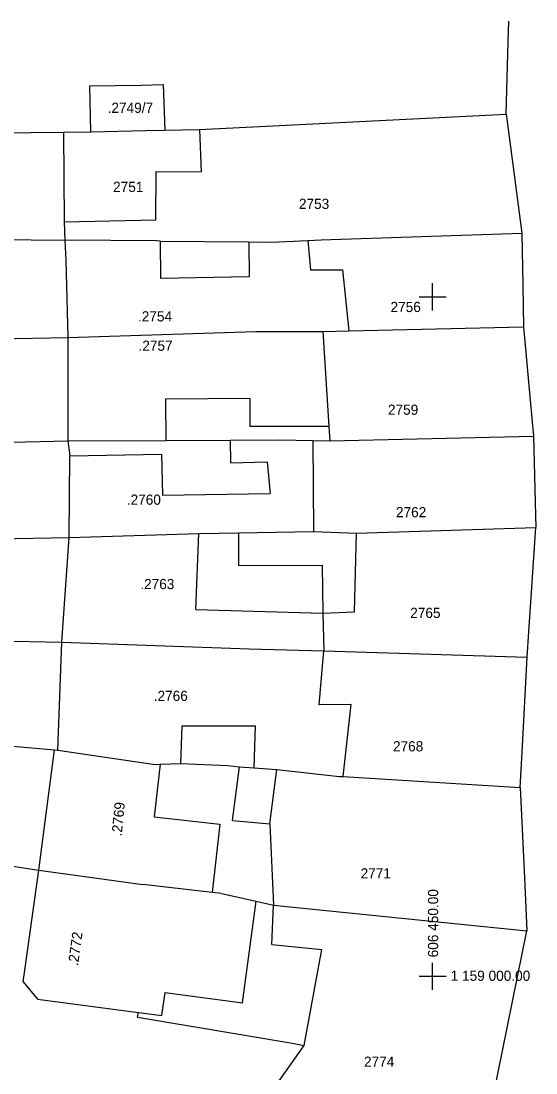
# Model space of a CAD drawing. Extents: x -606541 to -606327, y -1159083 to -1158785.
# Drawn here: x -606480.3 to -606442.4, y -1159007.1 to -1158929.7 of the extents above; entities that cross this region are included whole.
import ezdxf

# ---------------------------------------------------------------- set-up
doc = ezdxf.new("R2010")
doc.units = 0
for name, color, linetype in [('KN_HRAN_PARCEL', 7, 'Continuous'), ('KN_PARC_Č', 7, 'Continuous'), ('KN_VKP_HRAN_', 7, 'Continuous'), ('TISK_rám', 7, 'Continuous')]:
    doc.layers.add(name, color=color, linetype=linetype)

msp = doc.modelspace()

# ---------------------------------------------------------------- linework, layer by layer
at = {"layer": 'KN_HRAN_PARCEL'}
for p, q in [((-606444.44, -1158931.2), (-606444.39, -1158929.7)), ((-606444.6, -1158936.55), (-606444.44, -1158931.2)), ((-606467.14, -1158937.69), (-606444.6, -1158936.55)), ((-606444.6, -1158936.55), (-606444.11, -1158940.26)), ((-606500.53, -1158938.03), (-606477.16, -1158937.89)), ((-606477.16, -1158937.89), (-606475.15, -1158937.85)), ((-606477.16, -1158937.89), (-606477.11, -1158944.48)), ((-606475.15, -1158937.85), (-606471.11, -1158937.77)), ((-606471.11, -1158937.77), (-606469.71, -1158937.74)), ((-606469.71, -1158937.74), (-606467.14, -1158937.69)), ((-606467.14, -1158937.69), (-606467.03, -1158940.79)), ((-606444.11, -1158940.26), (-606443.44, -1158945.32)), ((-606470.36, -1158944.33), (-606470.33, -1158940.78)), ((-606470.33, -1158940.78), (-606467.03, -1158940.79)), ((-606477.11, -1158944.48), (-606470.36, -1158944.33)), ((-606477.11, -1158944.48), (-606477.06, -1158945.82)), ((-606500.28, -1158945.63), (-606477.06, -1158945.82)), ((-606458.19, -1158945.8), (-606443.44, -1158945.32)), ((-606443.44, -1158945.32), (-606443.37, -1158949.17)), ((-606477.06, -1158945.82), (-606476.98, -1158947.31)), ((-606470.03, -1158945.89), (-606463.52, -1158945.96)), ((-606463.52, -1158945.96), (-606461.82, -1158945.98)), ((-606461.82, -1158945.98), (-606459.18, -1158945.85)), ((-606459.18, -1158945.85), (-606458.19, -1158945.8)), ((-606459.18, -1158945.85), (-606458.99, -1158948)), ((-606476.98, -1158947.31), (-606476.83, -1158952.99)), ((-606458.99, -1158948), (-606456.64, -1158948.02)), ((-606456.64, -1158948.02), (-606456.17, -1158952.51)), ((-606443.37, -1158949.17), (-606443.31, -1158952.2)), ((-606476.83, -1158952.99), (-606463, -1158952.55)), ((-606463, -1158952.55), (-606461.3, -1158952.56)), ((-606461.3, -1158952.56), (-606458.09, -1158952.56)), ((-606458.09, -1158952.56), (-606456.17, -1158952.51)), ((-606458.09, -1158952.56), (-606457.64, -1158959.54)), ((-606456.17, -1158952.51), (-606443.31, -1158952.2)), ((-606443.31, -1158952.2), (-606442.83, -1158957.61)), ((-606488.53, -1158953.22), (-606476.83, -1158952.99)), ((-606476.83, -1158952.99), (-606476.84, -1158960.59)), ((-606442.83, -1158957.61), (-606442.59, -1158960.25)), ((-606457.64, -1158959.54), (-606457.57, -1158960.6)), ((-606457.57, -1158960.6), (-606442.59, -1158960.25)), ((-606442.59, -1158960.25), (-606442.43, -1158966.06)), ((-606499.03, -1158961.12), (-606476.84, -1158960.59)), ((-606476.84, -1158960.59), (-606469.62, -1158960.58)), ((-606476.84, -1158960.59), (-606476.7, -1158961.71)), ((-606469.62, -1158960.58), (-606464.9, -1158960.55)), ((-606464.9, -1158960.55), (-606461.28, -1158960.53)), ((-606461.28, -1158960.53), (-606458.82, -1158960.57)), ((-606458.82, -1158960.57), (-606457.57, -1158960.6)), ((-606458.82, -1158960.57), (-606458.76, -1158967.26)), ((-606476.74, -1158967.72), (-606476.7, -1158961.71)), ((-606442.43, -1158966.06), (-606442.4, -1158966.98)), ((-606467.2, -1158967.42), (-606464.25, -1158967.37)), ((-606464.25, -1158967.37), (-606458.76, -1158967.26)), ((-606458.76, -1158967.26), (-606455.6, -1158967.38)), ((-606455.74, -1158973.17), (-606455.6, -1158967.38)), ((-606455.6, -1158967.38), (-606442.4, -1158966.98)), ((-606442.92, -1158974.66), (-606442.4, -1158966.98)), ((-606497.39, -1158968.08), (-606476.74, -1158967.72)), ((-606477.27, -1158975.41), (-606476.74, -1158967.72)), ((-606476.74, -1158967.72), (-606467.2, -1158967.42)), ((-606458.08, -1158973.27), (-606455.74, -1158973.17)), ((-606458.08, -1158973.27), (-606458.01, -1158976.04)), ((-606495.54, -1158975.04), (-606477.27, -1158975.41)), ((-606443.04, -1158976.52), (-606442.92, -1158974.66)), ((-606477.58, -1158983.35), (-606477.27, -1158975.41)), ((-606477.27, -1158975.41), (-606463.51, -1158975.9)), ((-606463.51, -1158975.9), (-606458.01, -1158976.04)), ((-606458.34, -1158980.03), (-606458.01, -1158976.04)), ((-606458.01, -1158976.04), (-606443.04, -1158976.52)), ((-606443.41, -1158983.5), (-606443.04, -1158976.52)), ((-606456, -1158980), (-606458.34, -1158980.03)), ((-606456.59, -1158985.31), (-606456, -1158980)), ((-606493.56, -1158982.01), (-606477.82, -1158983.33)), ((-606478.97, -1158992.18), (-606477.82, -1158983.33)), ((-606477.82, -1158983.33), (-606477.58, -1158983.35)), ((-606477.58, -1158983.35), (-606470.41, -1158984.41)), ((-606443.55, -1158986.11), (-606443.41, -1158983.5)), ((-606470.41, -1158984.41), (-606470.04, -1158984.4)), ((-606470.04, -1158984.4), (-606468.53, -1158984.34)), ((-606468.53, -1158984.34), (-606465.06, -1158984.49)), ((-606465.06, -1158984.49), (-606464.22, -1158984.58)), ((-606464.22, -1158984.58), (-606463.16, -1158984.66)), ((-606463.16, -1158984.66), (-606461.47, -1158984.78)), ((-606461.99, -1158988.77), (-606461.47, -1158984.78)), ((-606461.47, -1158984.78), (-606456.86, -1158985.29)), ((-606456.86, -1158985.29), (-606456.59, -1158985.31)), ((-606456.59, -1158985.31), (-606443.55, -1158986.11)), ((-606443.55, -1158986.11), (-606443.25, -1158992.76)), ((-606461.99, -1158988.77), (-606461.71, -1158994.77)), ((-606492.87, -1158990.06), (-606478.97, -1158992.18)), ((-606479.96, -1158999.21), (-606478.97, -1158992.18)), ((-606478.97, -1158992.18), (-606471.31, -1158993.25)), ((-606443.25, -1158992.76), (-606443.07, -1158996.65)), ((-606466.22, -1158993.83), (-606471.31, -1158993.25)), ((-606465.53, -1158993.91), (-606466.22, -1158993.83)), ((-606465.53, -1158993.91), (-606462.99, -1158994.48)), ((-606462.99, -1158994.48), (-606461.71, -1158994.77)), ((-606461.83, -1158997.67), (-606461.71, -1158994.77)), ((-606461.71, -1158994.77), (-606443.07, -1158996.65)), ((-606447.19, -1159016.89), (-606443.07, -1158996.65)), ((-606461.83, -1158997.67), (-606458.15, -1158998.04)), ((-606459.46, -1159005.09), (-606458.15, -1158998.04)), ((-606480.13, -1159000.4), (-606479.96, -1158999.21)), ((-606480.13, -1159000.4), (-606479.08, -1159001.68)), ((-606479.08, -1159001.68), (-606471.64, -1159002.66)), ((-606471.71, -1159003.01), (-606471.64, -1159002.66)), ((-606471.71, -1159003.01), (-606460.46, -1159004.91)), ((-606464.38, -1159012.06), (-606459.46, -1159005.09)), ((-606460.46, -1159004.91), (-606459.46, -1159005.09))]:
    msp.add_line(p, q, dxfattribs=at)
for points in [[(-606475.15, -1158937.85), (-606475.22, -1158934.48), (-606471.45, -1158934.41)], [(-606471.45, -1158934.41), (-606469.82, -1158934.38), (-606469.71, -1158937.74)], [(-606470.03, -1158945.89), (-606470.32, -1158945.88), (-606477.06, -1158945.82)]]:
    msp.add_lwpolyline(points, dxfattribs=at)
at = {"layer": 'KN_VKP_HRAN_'}
for p, q in [((-606469.99, -1158948.66), (-606470.03, -1158945.89)), ((-606463.52, -1158945.96), (-606463.5, -1158948.52)), ((-606463.5, -1158948.52), (-606469.99, -1158948.66)), ((-606463.42, -1158957.49), (-606469.65, -1158957.53)), ((-606469.65, -1158957.53), (-606469.62, -1158960.58)), ((-606463.43, -1158959.54), (-606463.42, -1158957.49)), ((-606457.64, -1158959.54), (-606463.43, -1158959.54)), ((-606464.9, -1158960.55), (-606464.88, -1158962.22)), ((-606476.7, -1158961.71), (-606469.94, -1158961.57)), ((-606469.94, -1158961.57), (-606469.88, -1158964.6)), ((-606464.88, -1158962.22), (-606462.17, -1158962.14)), ((-606462.17, -1158962.14), (-606461.96, -1158964.46)), ((-606469.88, -1158964.6), (-606461.96, -1158964.46)), ((-606464.26, -1158969.77), (-606464.25, -1158967.37)), ((-606467.43, -1158973.01), (-606467.2, -1158967.42)), ((-606464.26, -1158969.77), (-606458.14, -1158969.74)), ((-606458.14, -1158969.74), (-606458.08, -1158973.27)), ((-606467.43, -1158973.01), (-606458.08, -1158973.27)), ((-606468.53, -1158984.34), (-606468.43, -1158981.56)), ((-606468.43, -1158981.56), (-606463.05, -1158981.58)), ((-606463.05, -1158981.58), (-606463.16, -1158984.66)), ((-606470.04, -1158984.4), (-606470.48, -1158988.27)), ((-606464.72, -1158988.53), (-606464.22, -1158984.58)), ((-606470.48, -1158988.27), (-606465.66, -1158988.8)), ((-606465.66, -1158988.8), (-606466.22, -1158993.83)), ((-606464.72, -1158988.53), (-606461.99, -1158988.77)), ((-606463.98, -1159001.95), (-606462.99, -1158994.48)), ((-606469.93, -1159002.89), (-606469.69, -1159001.19)), ((-606469.69, -1159001.19), (-606463.98, -1159001.95)), ((-606471.64, -1159002.66), (-606469.93, -1159002.89))]:
    msp.add_line(p, q, dxfattribs=at)
at = {"layer": 'TISK_rám'}
for p, q in [((-606450, -1158951), (-606450, -1158949)), ((-606451, -1158950), (-606449, -1158950)), ((-606450, -1159001), (-606450, -1158999)), ((-606450, -1159001), (-606450, -1158999)), ((-606450, -1159001), (-606450, -1158999)), ((-606450, -1159001), (-606450, -1158999)), ((-606451, -1159000), (-606449, -1159000)), ((-606451, -1159000), (-606449, -1159000)), ((-606451, -1159000), (-606449, -1159000)), ((-606451, -1159000), (-606449, -1159000))]:
    msp.add_line(p, q, dxfattribs=at)

# ---------------------------------------------------------------- texts
at = {"layer": 'KN_PARC_Č'}
for s, p in [('.2749/7', (-606473.91, -1158936.46)), ('2751', (-606473.51, -1158942.28)), ('2753', (-606459.84, -1158943.53)), ('2756', (-606453.1, -1158951.12)), ('.2754', (-606471.68, -1158951.81)), ('.2757', (-606471.64, -1158953.97)), ('2759', (-606453.29, -1158958.68)), ('.2760', (-606472.5, -1158965.3)), ('2762', (-606452.7, -1158966.22)), ('.2763', (-606471.51, -1158971.51)), ('2765', (-606451.65, -1158973.63)), ('.2766', (-606470.52, -1158979.74)), ('2768', (-606452.92, -1158983.45)), ('2771', (-606455.3, -1158992.8)), ('2774', (-606455.05, -1159006.66))]:
    msp.add_text(s, height=0.75, dxfattribs=at).set_placement(p)
for s, rotation, p in [('.2769', 84.48509, (-606472.88, -1158989.72)), ('.2772', 82.29917, (-606476.09, -1158999.27))]:
    msp.add_text(s, height=0.75, rotation=rotation, dxfattribs=at).set_placement(p)
at = {"layer": 'TISK_rám'}
msp.add_text('606 450.00', height=0.75, rotation=90, dxfattribs=at).set_placement((-606449.594, -1158998.605))
msp.add_text('1 159 000.00', height=0.75, dxfattribs=at).set_placement((-606448.674, -1159000.335))

doc.saveas('drawing.dxf')
